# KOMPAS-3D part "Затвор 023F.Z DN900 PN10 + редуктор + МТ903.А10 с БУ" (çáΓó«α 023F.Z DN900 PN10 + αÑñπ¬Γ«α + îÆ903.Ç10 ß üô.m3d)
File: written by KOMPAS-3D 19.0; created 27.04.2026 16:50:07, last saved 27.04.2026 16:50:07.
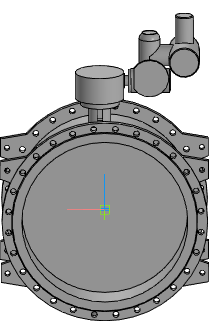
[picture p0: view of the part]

Document properties: Полное имя файла: ..\..\Затвор 023F.Z DN400-DN1600 + редуктор + МТ903\Затвор 023F.Z DN900 PN10 + редуктор + МТ903.А10 с БУ.a3d

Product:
- Part/product: Затвор 023F.Z DN900 PN10 + редуктор + МТ903.А10 с БУ
    Масса: 1077.18

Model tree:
1. Операция без истории:1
